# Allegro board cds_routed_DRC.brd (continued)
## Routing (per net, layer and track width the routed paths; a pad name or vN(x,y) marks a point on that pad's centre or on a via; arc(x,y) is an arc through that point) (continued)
RD2: length 121.8
  TOP w0.127: v1(112.52,68.73) v1(88.27,68.73) ; U16.10 v1(113.03,77.11) ; U15.10 v1(88.27,101.78) ; U14.10 v1(88.27,76.38) ; v1(112.52,86.16) 113.03,86.66 U17.10 ; v1(88.27,104.39) 88.24,104.42 61.32,104.42 55.88,98.98 U5.83
  BOTTOM w0.127: v1(113.03,77.11) 112.52,77.11 ; 112.52,77.11 v1(112.52,68.73) ; 112.52,77.11 v1(112.52,86.16) ; v1(88.27,104.39) v1(88.27,101.78) v1(88.27,76.38) v1(88.27,68.73)
RD3: length 110.6
  TOP w0.127: U15.7 v1(84.45,101.78) ; v1(85.5,91.11) 71.83,91.11 69.09,93.85 56.13,93.85 54.61,95.38 U5.84 ; U16.7 v1(109.22,76.38) 108.03,77.57 91.82,77.57 90.04,75.79 90.04,73.71 85.17,73.71 84.45,74.42 U14.7 v1(84.45,76.38) ; U17.7 v1(109.22,89.28)
  BOTTOM w0.127: 84.45,93.14 85.47,93.14 85.72,92.89 85.72,91.34 v1(85.5,91.11) ; 84.45,93.14 83.95,92.63 83.95,76.89 v1(84.45,76.38) ; 84.45,93.14 v1(84.45,101.78) ; v1(109.22,89.28) v1(109.22,76.38)
RD4: length 138.2
  TOP w0.127: v1(83.95,95.71) 84.45,96.22 U13.26 ; U12.26 109.22,70.48 108.23,69.49 85.27,69.49 v1(84.45,70.31) U10.26 ; U5.1 53.34,99.92 51.03,102.23 51.03,106.2 51.64,106.81 83.26,106.81 v1(83.95,107.49) 107.37,107.49 109.22,109.35 U11.26
  BOTTOM w0.127: v1(84.45,70.31) 83.69,71.07 83.69,95.45 v1(83.95,95.71) v1(83.95,107.49)
RD5: length 151.9
  TOP w0.127: U10.23 88.27,72.21 88.01,72.47 87.76,72.47 ; v1(52.07,105.82) v1(87.73,105.82) 110.49,105.82 113.03,108.36 U11.23 ; 87.76,72.47 87.76,72.72 87.5,72.97 83.95,72.97 83.95,69.49 84.2,69.24 111.79,69.24 113.03,70.48 U12.23 ; 87.76,72.47 v1(87.76,70.31) ; U5.2 v1(52.07,97.89) ; v1(87.76,95.71) 88.27,96.22 U13.23
  BOTTOM w0.127: v1(52.07,97.89) v1(52.07,105.82) ; v1(87.76,70.31) v1(87.76,95.71) 87.73,95.73 v1(87.73,105.82)
RD6: length 143.8
  TOP w0.127: U12.10 113.03,64.77 109.78,68.02 v1(89.31,68.02) ; U11.10 113.03,99.14 113.54,98.63 113.54,93.57 111,91.03 94.36,91.03 92.84,89.51 92.84,86.66 92.58,86.41 88.27,86.41 ; U13.10 88.27,86.41 ; 88.27,86.41 85.24,86.41 84.99,86.66 v1(84.99,89.81) 72.64,89.81 71.86,89.03 53.34,89.03 50.8,91.57 U5.3 ; U10.10 v1(88.27,63.68)
  BOTTOM w0.127: 88.27,68.02 v1(89.31,68.02) ; 88.27,68.02 v1(88.27,63.68) ; 88.27,68.02 86.49,69.8 86.49,89.59 85.75,90.32 85.5,90.32 v1(84.99,89.81)
RD7: length 151.9
  TOP w0.127: 85.22,93.42 85.22,98.37 104.65,98.37 104.9,98.12 104.9,95.94 105.16,95.68 108.2,95.68 108.71,96.19 108.71,98.63 109.22,99.14 U11.7 ; 85.22,93.42 v1(85.22,92.63) ; 85.22,93.42 80.9,93.42 78.87,95.45 78.87,98.09 77.85,99.11 57.91,99.11 57.66,98.86 57.66,95.22 55.37,95.22 55.37,97.41 55.12,97.66 54.1,97.66 54.1,95.48 53.85,95.22 52.83,95.22 52.83,98.07 52.5,98.4 49.89,98.4 49.53,98.04 U5.4 ; U10.7 v1(84.45,60.78) ; U13.7 v1(84.45,89.08) ; U12.7 v1(109.22,60.05)
  BOTTOM w0.127: v1(109.22,60.05) 86.97,60.05 86.23,60.78 ; 86.23,60.78 86.23,87.3 v1(84.45,89.08) 84.45,91.87 v1(85.22,92.63) ; 86.23,60.78 v1(84.45,60.78)
RDY: length 41
  TOP w0.127: J1.50 14.48,62.74 40.77,62.74 45.82,57.68 45.82,55.14 U2.23
RESET: length 44.4
  TOP w0.127: J1.53 24.41,68.58 26.95,71.12 26.95,86.56 31.19,90.8 U5.15
RWE: length 143.8
  TOP w0.127: v1(114.81,98.88) 114.3,99.39 U11.11 ; 114.81,76.89 118.36,76.89 118.87,76.38 118.87,68.1 114.3,63.53 U12.11 ; 114.81,76.89 v1(114.81,89.08) 114.3,88.57 U17.11 ; 114.81,76.89 114.3,76.89 ; 114.3,76.89 U16.11 ; 114.3,76.89 113.36,77.83 89.79,77.83 89.53,77.57 89.53,76.89 ; 89.53,76.89 77.09,76.89 75.06,74.85 v1(75.06,73.74) ; 89.53,76.89 v1(89.53,76.38) U14.11 ; U13.11 v1(89.53,89.08) ; U10.11 89.53,63.17 v1(90.04,63.68) ; U5.57 69.09,73.02 v1(69.72,73.66) ; v1(90.04,101.78) 89.53,101.27 U15.11
  BOTTOM w0.127: 90.04,89.08 v1(89.53,89.08) ; 90.04,89.08 v1(90.04,101.78) ; 90.04,89.08 90.04,76.38 ; 90.04,76.38 v1(89.53,76.38) ; 90.04,76.38 v1(90.04,63.68) ; v1(75.06,73.74) 75.06,73.66 v1(69.72,73.66) ; v1(114.81,98.88) v1(114.81,89.08)
SEL: length 74.6
  TOP w0.127: U5.13 41.35,93.34 47.02,87.68 v1(47.02,72.09)
  BOTTOM w0.127: U2.14 47.62,31.67 53.11,37.16 53.11,69.55 50.57,72.09 v1(47.02,72.09)
V+12: length 227.5
  TOP w0.381: J1.64 J1.63 11.28,92.56 7.04,92.56 6.02,91.54 6.02,25.04 6.93,24.13 101.64,24.13 101.89,23.88 v1(102.51,23.88) ; U20.7 104.78,20.32 U23.4 v1(101.09,20.32) ; v1(105.49,40) U19.4 v1(101.42,40)
  BOTTOM w0.381: C28.1 99.97,9.88 98.81,9.88 97.79,10.9 97.79,15.88 100.25,18.34 100.76,18.34 101.09,18.67 v1(101.09,20.32) 102.51,21.74 v1(102.51,23.88) 102.51,27.3 ; 102.51,27.3 102.51,38.91 v1(101.42,40) ; 102.51,27.3 C25.1 ; 107.31,36.83 105.49,38.66 v1(105.49,40)
VCLKA: length 82.6
  TOP w0.203: U18.11 76.35,40.64 74.47,42.52 71.35,42.52 ; 71.35,42.52 58.78,42.52 48.92,52.37 48.92,59.99 41.91,67.01 U5.34 ; 71.35,42.52 71.35,30.68 72.82,29.21 U8.11 v1(76.28,29.21) ; U21.11 v1(76.28,20.32)
  BOTTOM w0.203: v1(76.28,20.32) v1(76.28,29.21)
VCLKC: length 89.4
  TOP w0.203: U9.11 v1(67.79,8.89)
  BOTTOM w0.203: v1(67.79,8.89) 67.79,62 65.25,64.54 60.22,64.54 51.69,73.08 43.48,73.08 R5.2
VD0: length 86.6
  TOP w0.127: U5.39 48.26,68.83 48.51,69.09 50.83,69.09 51.56,68.35 51.56,56.64 52.32,55.88 v1(62.69,55.88) U6.2 ; U9.2 v1(59.87,19.05) ; U8.2 v1(61.39,39.37)
  BOTTOM w0.127: v1(59.87,19.05) 59.87,21.59 ; 59.87,21.59 59.87,37.85 v1(61.39,39.37) 61.39,54.58 v1(62.69,55.88) ; 59.87,21.59 R9.2
VD1: length 87.5
  TOP w0.127: v1(54.48,19.05) 55.75,17.78 v1(62.69,17.78) U9.3 ; U5.40 49.53,56.9 51.82,54.61 v1(62.69,54.61) U6.3 ; v1(63.2,41.38) 65.79,41.38 66.09,41.07 66.09,38.85 65.34,38.1 U8.3
  BOTTOM w0.127: v1(62.69,54.61) 63.2,54.1 v1(63.2,41.38) 63.2,18.29 v1(62.69,17.78) ; R13.2 v1(54.48,19.05)
VD2: length 97.1
  TOP w0.127: U9.4 v1(62.69,16.51) v1(49.15,16.51) ; U6.4 65.34,53.34 65.58,53.58 v1(65.58,54.33) 65.58,54.84 65.2,55.22 51.71,55.22 50.8,56.13 U5.41 ; U8.4 63.63,36.83 61.72,34.92 61.72,29.24 62.74,28.22 v1(64.57,28.22)
  BOTTOM w0.127: v1(65.58,54.33) 64.57,53.31 v1(64.57,28.22) 64.57,17.63 63.45,16.51 v1(62.69,16.51) ; R8.2 v1(49.15,16.51)
VD3: length 85.9
  TOP w0.127: U8.5 v1(65.76,35.56) ; U5.42 52.07,59.18 54.61,56.64 65.07,56.64 66.09,55.63 66.09,52.58 v1(65.58,52.07) U6.5 ; U9.5 v1(62.69,15.24) 56.01,15.24 v1(54.74,13.97)
  BOTTOM w0.127: v1(65.58,52.07) 65.07,51.56 65.07,35.56 ; R12.2 v1(54.74,13.97) ; 65.07,35.56 65.07,17.63 v1(62.69,15.24) ; 65.07,35.56 v1(65.76,35.56)
VD4: length 90.6
  TOP w0.127: U8.6 v1(65.58,34.29) ; U9.6 v1(65.58,13.97) ; U5.43 53.34,60.96 55.88,58.42 64.57,58.42 66.34,56.64 v1(66.34,51.03) 66.12,50.8 U6.6
  BOTTOM w0.127: v1(66.34,51.03) 66.34,35.05 v1(65.58,34.29) v1(65.58,13.97) 65.58,12.19 63.04,9.65 62.43,9.65 60.66,11.43 R7.2
VD5: length 100.9
  TOP w0.127: U5.44 54.61,60.96 56.13,59.44 65.84,59.44 66.85,58.42 66.85,50.8 65.58,49.53 U6.7 v1(61.93,49.53) ; U9.7 v1(60.38,12.7) ; v1(61.93,37.34) 65.25,37.34 66.27,36.32 66.27,34.14 65.15,33.02 U8.7
  BOTTOM w0.127: R11.2 47.12,9.78 47.12,12.45 47.37,12.7 v1(60.38,12.7) 60.38,35.79 v1(61.93,37.34) v1(61.93,49.53)
VD6: length 100.3
  TOP w0.127: U8.8 v1(67.08,31.75) ; U5.45 55.88,62.74 58.42,60.2 65.58,60.2 67.11,58.67 67.11,48.29 v1(67.08,48.26) U6.8 ; v1(61.39,6.35) 61.39,10.59 62.23,11.43 U9.8
  BOTTOM w0.127: R6.2 v1(61.39,6.35) 63.93,6.35 67.08,9.5 v1(67.08,31.75) v1(67.08,48.26)
VD7: length 94.8
  TOP w0.127: v1(63.7,44.98) 62.92,44.98 62.66,45.24 62.66,46.74 62.92,46.99 U6.9 ; v1(62.64,3.81) v1(62.64,10.16) U9.9 ; U5.46 v1(57.15,63.25) ; U8.9 64.64,30.48 65.61,29.51 65.61,28.35 64.72,27.46 v1(63.7,27.46)
  BOTTOM w0.127: R10.2 v1(62.64,3.81) ; v1(62.64,10.16) 61.87,10.92 61.87,16.51 62.64,17.27 63.14,17.27 63.7,17.83 v1(63.7,27.46) v1(63.7,44.98) 63.7,59.23 59.69,63.25 v1(57.15,63.25)
VREF: length 35
  TOP w0.127: L5.1 113.18,3.96 101.88,3.96 100.97,4.88 R14.1
  BOTTOM w0.127: L3.1 115.16,23.27 115.16,5.94 L5.1
WAIT: length 29.5
  TOP w0.127: U5.33 36.75,63.5 J1.51
WSTAT: length 31.5
  TOP w0.127: U6.11 v1(69.82,45.72) ; U5.56 v1(69.82,71.75)
  BOTTOM w0.127: v1(69.82,71.75) v1(69.82,45.72)
N14843: length 3.2
  BOTTOM w0.127: C13.1 R12.1
N14849: length 3.2
  BOTTOM w0.127: C9.1 R8.1
N14853: length 3.2
  BOTTOM w0.127: C14.1 R13.1
N14855: length 3.2
  BOTTOM w0.127: R9.1 C10.1
N15143: length 3.2
  BOTTOM w0.127: C11.1 R10.1
N15151: length 3.2
  BOTTOM w0.127: C7.1 R6.1
N15155: length 3.2
  BOTTOM w0.127: C12.1 R11.1
N15161: length 3.2
  BOTTOM w0.127: C8.1 R7.1
N58063: length 5.7
  TOP w0.127: U8.19 U18.12
N58118: length 5.7
  TOP w0.127: U8.18 U18.13
N58173: length 5.7
  TOP w0.127: U8.17 U18.14
N58228: length 5.7
  TOP w0.127: U8.16 U18.15
N58283: length 5.7
  TOP w0.127: U8.15 U18.16
N58338: length 5.7
  TOP w0.127: U8.14 U18.17
N58393: length 5.7
  TOP w0.127: U8.13 U18.18
N58448: length 5.7
  TOP w0.127: U8.12 U18.19
N58834: length 6.4
  TOP w0.127: U9.19 U21.12
N58889: length 6.4
  TOP w0.127: U9.18 U21.13
N58944: length 6.4
  TOP w0.127: U9.17 U21.14
N58999: length 6.4
  TOP w0.127: U9.16 U21.15
N59054: length 6.4
  TOP w0.127: U9.15 U21.16
N59109: length 6.4
  TOP w0.127: U9.14 U21.17
N59164: length 6.4
  TOP w0.127: U9.13 U21.18
N59219: length 6.4
  TOP w0.127: U9.12 U21.19
N409523: length 4.9
  TOP w0.127: U5.37 v1(45.72,68.83)
  BOTTOM w0.127: R5.1 45.72,70.48 v1(45.72,68.83)

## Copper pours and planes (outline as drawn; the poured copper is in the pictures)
GND on GND: 2.03,107.82 22.99,107.82 23.11,107.95 23.11,111.89 24,112.78 124.08,112.78 124.08,1.52 23.37,1.52 22.99,1.91 22.99,6.48 22.86,6.6 1.78,6.6 1.4,6.99 1.4,107.19
VCC on VCC (solid shape): 124.33,112.39 124.33,1.91 123.82,1.4 23.62,1.4 22.99,2.03 22.99,6.48 22.86,6.6 1.9,6.6 1.4,7.11 1.4,107.19 1.9,107.7 23.11,107.7 23.11,112.52 23.37,112.78 123.95,112.78

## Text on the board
DIMENSION: FIGURE | FINISHED_SIZE | 13.0 | 31.0 | 38.0 | 75.0 | 110.0 | DRILL CHART: TOP to BOTTOM | ALL UNITS ARE IN MILS | DRILLED_SIZE | - | PLATED | NON-PLATED | QTY | 506 | 12 | 122 | 8 | 5
